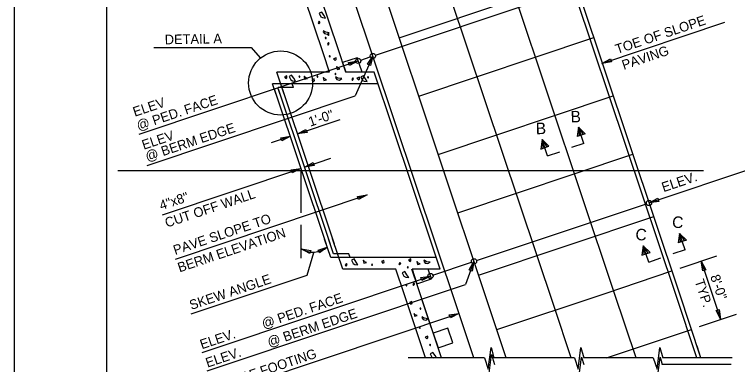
# Model space of a CAD drawing. Extents: x 0 to 272, y 0 to 188.
# Drawn here: x 0 to 94, y 79 to 124.5 of the extents above; entities that cross this region are included whole.
import ezdxf

# ---------------------------------------------------------------- set-up
doc = ezdxf.new("R2010")
doc.units = 0
for name, color, linetype in [('BORDER_ANNO_Cutsheet', 7, 'Continuous'), ('BRDG_ANNO_Anno-Sheet', 7, 'Continuous'), ('BRDG_ANNO_General-Notes', 7, 'Continuous'), ('BRDG_BASE_Hidden-Line', 7, 'Continuous'), ('BRDG_BASE_Obj-Line', 7, 'Continuous'), ('BRDG_BASE_Pattern', 7, 'Continuous'), ('BRDG_BASE_Roadway-Center-Lines', 7, 'Continuous')]:
    doc.layers.add(name, color=color, linetype=linetype)

msp = doc.modelspace()

# ---------------------------------------------------------------- linework, layer by layer
at = {"layer": 'BORDER_ANNO_Cutsheet'}
msp.add_lwpolyline([(0, 176), (272, 176), (272, 0), (0, 0)], close=True, dxfattribs=at)
at = {"layer": 'BRDG_ANNO_Anno-Sheet'}
msp.add_lwpolyline([(12, 172), (268, 172), (268, 4), (12, 4)], close=True, dxfattribs=at)
at = {"layer": 'BRDG_ANNO_General-Notes'}
for p, q in [((46.932, 119.228), (72.827, 127.893)), ((76.371, 118.156), (92.332, 123.497)), ((18.102, 120.234), (30.764, 120.234)), ((30.764, 120.234), (31.942, 118.866)), ((16.198, 108.945), (44.691, 118.478)), ((43.439, 118.279), (44.691, 118.478)), ((44.691, 118.478), (43.572, 117.884)), ((46.588, 119.099), (44.279, 113.92)), ((45.012, 118.586), (46.239, 118.996)), ((45.889, 118.043), (46.588, 119.099)), ((46.588, 119.099), (46.27, 117.873)), ((76.371, 118.156), (77.491, 118.75)), ((77.491, 118.75), (77.623, 118.355)), ((43.572, 117.884), (43.439, 118.279)), ((46.27, 117.873), (45.889, 118.043)), ((77.623, 118.355), (76.371, 118.156)), ((17.263, 104.88), (44.279, 113.92)), ((36.78, 108.983), (42.345, 110.845)), ((36.78, 108.983), (37.899, 109.578)), ((38.031, 109.182), (36.78, 108.983)), ((37.899, 109.578), (38.031, 109.182)), ((73.309, 109.876), (73.135, 108.63)), ((74.027, 107.744), (73.309, 109.876)), ((73.309, 109.876), (74.201, 108.989)), ((73.309, 109.876), (73.401, 108.72)), ((73.309, 109.876), (73.934, 108.9)), ((33.425, 107.861), (35.866, 108.678)), ((34.614, 108.478), (35.866, 108.678)), ((34.747, 108.083), (34.614, 108.478)), ((35.866, 108.678), (34.747, 108.083)), ((68.583, 108.267), (68.409, 107.022)), ((69.301, 106.135), (68.583, 108.267)), ((68.583, 108.267), (69.475, 107.381)), ((68.583, 108.267), (69.208, 107.291)), ((68.583, 108.267), (68.675, 107.112)), ((73.668, 108.81), (73.135, 108.63)), ((74.201, 108.989), (73.668, 108.81)), ((68.409, 107.022), (68.942, 107.201)), ((68.942, 107.201), (69.475, 107.381)), ((74.027, 107.744), (72.427, 107.205)), ((69.301, 106.135), (70.9, 106.673)), ((37.701, 104.67), (41.147, 105.824)), ((19.225, 98.488), (37.211, 104.506)), ((35.959, 104.307), (37.211, 104.506)), ((37.211, 104.506), (36.091, 103.912)), ((37.701, 104.67), (38.82, 105.265)), ((38.952, 104.869), (37.701, 104.67)), ((38.82, 105.265), (38.952, 104.869)), ((82.502, 100.022), (97.115, 104.912)), ((36.091, 103.912), (35.959, 104.307)), ((37.284, 98.712), (37.284, 104.251)), ((20.955, 92.725), (45.834, 101.049)), ((44.583, 100.85), (45.834, 101.049)), ((44.715, 100.455), (44.583, 100.85)), ((45.834, 101.049), (44.715, 100.455)), ((82.502, 100.022), (83.621, 100.616)), ((83.621, 100.616), (83.753, 100.221)), ((60.083, 92.521), (82.166, 99.91)), ((83.753, 100.221), (82.502, 100.022)), ((37.284, 92.855), (37.284, 97.18)), ((86.458, 96.061), (86.283, 94.815)), ((87.175, 93.929), (86.458, 96.061)), ((86.458, 96.061), (87.35, 95.174)), ((86.458, 96.061), (86.55, 94.905)), ((86.458, 96.061), (87.083, 95.085)), ((86.816, 94.995), (86.283, 94.815)), ((87.35, 95.174), (86.816, 94.995)), ((38.393, 93.434), (37.284, 94.047)), ((37.284, 94.047), (38.532, 93.827)), ((39.461, 93.885), (40.672, 94.257)), ((40.672, 94.257), (39.647, 93.512)), ((81.731, 94.453), (81.557, 93.207)), ((82.449, 92.32), (81.731, 94.453)), ((81.731, 94.453), (82.623, 93.566)), ((81.731, 94.453), (82.357, 93.476)), ((81.731, 94.453), (81.824, 93.297)), ((38.062, 90.648), (38.906, 93.579)), ((38.532, 93.827), (38.393, 93.434)), ((39.647, 93.512), (39.461, 93.885)), ((81.557, 93.207), (82.09, 93.386)), ((82.09, 93.386), (82.623, 93.566)), ((87.175, 93.929), (85.576, 93.39)), ((86.523, 91.524), (91.305, 93.124)), ((54.396, 90.618), (59.412, 92.296)), ((59.732, 92.406), (58.643, 89.43)), ((59.106, 91.304), (59.732, 92.406)), ((59.732, 92.406), (59.498, 91.161)), ((82.449, 92.32), (84.048, 92.858)), ((89.287, 92.449), (91.804, 84.926)), ((89.486, 91.197), (89.287, 92.449)), ((89.287, 92.449), (89.881, 91.33)), ((59.498, 91.161), (59.106, 91.304)), ((89.881, 91.33), (89.486, 91.197)), ((22.98, 85.602), (38.062, 90.648)), ((24.386, 80.577), (54.092, 90.516)), ((52.84, 90.317), (54.092, 90.516)), ((52.972, 89.922), (52.84, 90.317)), ((54.092, 90.516), (52.972, 89.922)), ((25.039, 78.187), (58.643, 89.43)), ((26.054, 75.048), (57.783, 85.664)), ((56.532, 85.465), (57.783, 85.664)), ((57.783, 85.664), (56.664, 85.07)), ((91.21, 86.045), (91.605, 86.177)), ((91.804, 84.926), (91.21, 86.045)), ((91.605, 86.177), (91.804, 84.926)), ((56.664, 85.07), (56.532, 85.465)), ((89.071, 83.941), (93.843, 85.538))]:
    msp.add_line(p, q, dxfattribs=at)
for centre, radius in [((34.602, 115.604), 4.162), ((46.588, 119.109), 0.343), ((82.491, 100.007), 0.343), ((59.74, 92.424), 0.343), ((54.08, 90.513), 0.343)]:
    msp.add_circle(centre, radius, dxfattribs=at)
msp.add_arc((38.824, 96.633), 3.01, 239.21951, 307.87987, dxfattribs=at)
at = {"layer": 'BRDG_BASE_Hidden-Line'}
for p, q in [((57.505, 86.496), (43.358, 128.776)), ((85.925, 88.224), (72.373, 128.728)), ((34.551, 114.128), (34.259, 115.001)), ((36.269, 115.005), (34.271, 115.005)), ((34.458, 114.405), (34.322, 114.812)), ((36.269, 115.005), (36.107, 115.492)), ((41.075, 94.631), (34.458, 114.405)), ((41.486, 93.402), (40.836, 95.344)), ((43.484, 93.402), (41.486, 93.402)), ((43.647, 92.915), (43.484, 93.402)), ((88.714, 79.889), (85.925, 88.224)), ((59.716, 79.889), (57.505, 86.496))]:
    msp.add_line(p, q, dxfattribs=at)
at = {"layer": 'BRDG_BASE_Obj-Line'}
for p, q in [((40.177, 119.375), (37.025, 128.794)), ((42.069, 120.024), (39.155, 128.733)), ((61.713, 86.525), (47.591, 128.731)), ((50.015, 121.488), (71.723, 128.752)), ((70.146, 86.534), (56.014, 128.772)), ((78.007, 88.253), (64.448, 128.776)), ((86.434, 88.278), (72.883, 128.778)), ((52.553, 113.902), (75.313, 121.517)), ((43.079, 117.005), (42.069, 120.024)), ((40.967, 117.013), (40.177, 119.375)), ((44.55, 118.887), (42.655, 118.246)), ((45.191, 116.993), (44.55, 118.887)), ((42.655, 118.246), (43.074, 117.01)), ((40.962, 117.005), (34.088, 117.005)), ((35.07, 114.153), (34.113, 117.013)), ((46.77, 117.005), (43.079, 117.005)), ((54.16, 94.918), (46.77, 117.005)), ((47.259, 115.505), (33.563, 115.505)), ((34.032, 114.102), (33.563, 115.505)), ((40.553, 94.612), (33.803, 114.787)), ((41.596, 94.649), (34.841, 114.838)), ((55.092, 106.315), (77.851, 113.93)), ((57.63, 98.728), (80.39, 106.344)), ((60.338, 90.633), (83.098, 98.248)), ((41.126, 92.902), (40.315, 95.326)), ((42.681, 91.406), (41.357, 95.362)), ((55.336, 91.402), (54.16, 94.918)), ((51.109, 92.902), (41.126, 92.902)), ((54.846, 92.902), (51.109, 92.902)), ((49.56, 91.402), (42.681, 91.402)), ((50.653, 88.203), (49.581, 91.409)), ((52.477, 88.978), (51.667, 91.397)), ((55.336, 91.402), (51.681, 91.402)), ((51.681, 91.402), (52.323, 89.508)), ((54.217, 90.149), (53.792, 91.404)), ((76.781, 88.265), (85.467, 91.171)), ((52.323, 89.508), (54.217, 90.149)), ((55.518, 79.889), (52.477, 88.978)), ((53.436, 79.889), (50.653, 88.203)), ((55.518, 79.889), (52.965, 87.52)), ((62.707, 83.555), (76.781, 88.265)), ((80.806, 79.889), (78.007, 88.253)), ((89.242, 79.889), (86.434, 88.278)), ((63.934, 79.889), (61.713, 86.525)), ((72.37, 79.889), (70.146, 86.534)), ((56.337, 83.738), (54.442, 83.097)), ((56.978, 81.844), (56.337, 83.738)), ((54.442, 83.097), (55.084, 81.202)), ((76.961, 79.889), (88.005, 83.584)), ((55.084, 81.202), (56.978, 81.844)), ((61.578, 78.4), (61.953, 81.206)), ((61.953, 81.206), (62.331, 79.879)), ((73.265, 78.4), (73.637, 81.205)), ((73.637, 81.205), (74.016, 79.881)), ((83.532, 78.402), (83.904, 81.207)), ((83.904, 81.207), (84.284, 79.883)), ((89.242, 79.889), (88.73, 81.417)), ((61.654, 77.529), (62.029, 80.336)), ((62.029, 80.336), (62.407, 79.009)), ((73.377, 77.281), (73.736, 79.988)), ((73.736, 79.988), (74.016, 79.01)), ((83.577, 77.281), (83.936, 79.99)), ((83.936, 79.99), (84.216, 79.012)), ((61.1, 79.88), (51.183, 79.88)), ((61.1, 79.88), (61.578, 78.4)), ((63.231, 79.879), (62.331, 79.879)), ((68.628, 79.879), (63.231, 79.879)), ((72.784, 79.879), (68.628, 79.879)), ((72.784, 79.879), (73.265, 78.4)), ((83.052, 79.881), (74.016, 79.881)), ((83.052, 79.881), (83.532, 78.402)), ((93.184, 79.013), (84.216, 79.012)), ((93.319, 79.883), (84.284, 79.883))]:
    msp.add_line(p, q, dxfattribs=at)
msp.add_circle((44.686, 118.477), 0.343, dxfattribs=at)
at = {"layer": 'BRDG_BASE_Pattern'}
for points in [[(39.606, 124.661), (39.831, 124.209), (40.057, 124.097), (40.45, 124.041), (40.225, 124.416), (39.944, 124.81)], [(39.472, 123.413), (39.565, 123.282), (39.677, 123.432), (39.696, 123.488), (39.603, 123.619)], [(40.13, 122.271), (40.299, 122.017), (40.646, 121.953), (40.928, 122.14), (40.491, 122.202), (40.154, 122.378)], [(40.374, 121.457), (40.445, 121.387), (40.501, 121.395), (40.501, 121.415), (40.501, 121.471), (40.482, 121.527), (40.449, 121.532), (40.421, 121.522), (40.412, 121.514), (40.399, 121.49)], [(40.745, 121.861), (40.815, 121.791), (40.871, 121.799), (40.871, 121.819), (40.871, 121.875), (40.852, 121.931), (40.82, 121.936), (40.792, 121.926), (40.782, 121.918), (40.769, 121.894)], [(40.684, 120.652), (40.777, 120.521), (40.889, 120.671), (40.908, 120.727), (40.815, 120.858)], [(40.907, 119.056), (40.977, 118.986), (41.033, 118.994), (41.033, 119.013), (41.033, 119.069), (41.014, 119.126), (40.981, 119.13), (40.953, 119.121), (40.944, 119.112), (40.931, 119.088)], [(41.485, 118.756), (41.676, 118.545), (41.826, 118.639), (41.808, 118.892)], [(41.864, 117.684), (41.93, 117.357), (42.282, 117.445), (42.024, 117.544), (41.893, 117.741)], [(35.694, 116.469), (35.919, 116.017), (36.145, 115.905), (36.538, 115.849), (36.313, 116.224), (36.032, 116.618)], [(41.647, 116.767), (41.718, 116.696), (41.773, 116.705), (41.773, 116.724), (41.773, 116.78), (41.754, 116.837), (41.722, 116.841), (41.694, 116.832), (41.684, 116.823), (41.671, 116.799)], [(35.088, 116.399), (35.279, 116.188), (35.429, 116.283), (35.412, 116.535)], [(36.968, 116.43), (37.038, 116.36), (37.094, 116.368), (37.094, 116.387), (37.094, 116.443), (37.075, 116.5), (37.042, 116.504), (37.014, 116.495), (37.005, 116.486), (36.992, 116.462)], [(37.656, 116.438), (37.721, 116.111), (38.074, 116.199), (37.815, 116.298), (37.685, 116.495)], [(38.657, 115.995), (38.848, 115.785), (38.998, 115.879), (38.98, 116.131)], [(39.324, 116.43), (39.395, 116.36), (39.45, 116.368), (39.45, 116.387), (39.45, 116.443), (39.431, 116.5), (39.399, 116.504), (39.371, 116.495), (39.361, 116.486), (39.348, 116.462)], [(40.147, 116.27), (40.213, 115.943), (40.565, 116.031), (40.307, 116.13), (40.176, 116.327)], [(41.739, 116.301), (41.909, 116.048), (42.255, 115.983), (42.537, 116.17), (42.1, 116.232), (41.763, 116.408)], [(43.842, 116.062), (43.935, 115.931), (44.047, 116.082), (44.067, 116.138), (43.973, 116.269)], [(44.515, 116.231), (44.706, 116.02), (44.856, 116.114), (44.838, 116.367)], [(45.019, 116.401), (45.245, 115.949), (45.47, 115.837), (45.864, 115.781), (45.639, 116.156), (45.358, 116.551)], [(45.889, 116.329), (45.96, 116.259), (46.016, 116.267), (46.016, 116.286), (46.016, 116.342), (45.996, 116.399), (45.964, 116.403), (45.936, 116.394), (45.926, 116.385), (45.913, 116.361)], [(43.012, 91.917), (43.106, 91.786), (43.218, 91.936), (43.237, 91.992), (43.144, 92.123)], [(43.811, 92.582), (44.037, 92.13), (44.262, 92.018), (44.656, 91.962), (44.431, 92.337), (44.149, 92.732)], [(45.348, 92.514), (45.414, 92.187), (45.766, 92.275), (45.508, 92.374), (45.377, 92.571)], [(47.707, 92.382), (47.898, 92.172), (48.048, 92.266), (48.03, 92.518)], [(49.982, 92.085), (50.075, 91.954), (50.187, 92.104), (50.207, 92.161), (50.113, 92.291)], [(51.208, 92.618), (51.399, 92.407), (51.549, 92.501), (51.532, 92.754)], [(52.317, 92.346), (52.383, 92.018), (52.735, 92.107), (52.477, 92.205), (52.346, 92.402)], [(53.223, 92.448), (53.393, 92.195), (53.74, 92.13), (54.021, 92.317), (53.584, 92.379), (53.247, 92.555)], [(46.414, 91.973), (46.484, 91.902), (46.54, 91.911), (46.54, 91.93), (46.54, 91.986), (46.521, 92.043), (46.488, 92.047), (46.46, 92.037), (46.451, 92.029), (46.438, 92.005)], [(51.06, 91.636), (51.13, 91.566), (51.186, 91.574), (51.186, 91.593), (51.186, 91.649), (51.167, 91.706), (51.135, 91.71), (51.106, 91.701), (51.097, 91.692), (51.084, 91.668)], [(50.41, 90.933), (50.635, 90.481), (50.861, 90.368), (51.254, 90.313), (51.029, 90.688), (50.748, 91.082)], [(50.891, 89.313), (50.962, 89.243), (51.018, 89.251), (51.018, 89.27), (51.018, 89.326), (50.998, 89.383), (50.966, 89.387), (50.938, 89.378), (50.928, 89.369), (50.916, 89.345)], [(51.8, 89.425), (51.893, 89.294), (52.005, 89.445), (52.025, 89.501), (51.931, 89.632)], [(51.346, 87.057), (51.537, 86.846), (51.687, 86.94), (51.669, 87.193)], [(51.95, 85.606), (52.016, 85.279), (52.368, 85.367), (52.109, 85.466), (51.979, 85.663)], [(52.712, 86.277), (52.783, 86.207), (52.839, 86.215), (52.839, 86.234), (52.839, 86.29), (52.819, 86.347), (52.787, 86.351), (52.759, 86.342), (52.749, 86.333), (52.736, 86.309)], [(52.957, 85.103), (53.126, 84.849), (53.473, 84.785), (53.755, 84.971), (53.318, 85.033), (52.981, 85.21)], [(52.611, 83.786), (52.682, 83.715), (52.737, 83.724), (52.737, 83.743), (52.737, 83.799), (52.718, 83.856), (52.686, 83.86), (52.658, 83.85), (52.648, 83.842), (52.635, 83.818)], [(53.399, 82.579), (53.591, 82.369), (53.741, 82.463), (53.723, 82.715)], [(53.958, 81.564), (54.028, 81.493), (54.084, 81.502), (54.084, 81.521), (54.084, 81.577), (54.065, 81.633), (54.033, 81.638), (54.005, 81.628), (53.995, 81.62), (53.982, 81.596)]]:
    msp.add_lwpolyline(points, close=True, dxfattribs=at)
for points in [[(54.844, 79.889), (54.671, 80.177), (54.389, 80.572), (54.051, 80.422)], [(54.051, 80.422), (54.277, 79.97), (54.441, 79.889)]]:
    msp.add_lwpolyline(points, dxfattribs=at)
at = {"layer": 'BRDG_BASE_Roadway-Center-Lines'}
for p, q in [((43.509, 104.189), (13.431, 104.189)), ((89.561, 104.189), (43.509, 104.189))]:
    msp.add_line(p, q, dxfattribs=at)

# ---------------------------------------------------------------- texts
at = {"layer": 'BRDG_ANNO_General-Notes'}
for s, height, rotation, p in [('TOE OF SLOPE', 1.25, 18.49999, (78.356, 119.357)), ('DETAIL A', 1.25, 1.1, (19.551, 120.625)), ('PAVING', 1.25, 18.49999, (79.213, 117.307)), ('ELEV  ', 1.25, 18.49992, (15.643, 111.209)), ('@ PED. FACE', 1.25, 18.49992, (16.114, 109.41)), ('1\'-0"', 1.25, 18.49998, (38.454, 109.92)), ('B', 1.5, 1.1, (72.31, 110.473)), ('@ BERM EDGE', 1.25, 18.49992, (17.257, 105.407)), ('B', 1.5, 1.1, (67.789, 108.942)), ('ELEV  ', 1.25, 18.49992, (16.808, 106.915)), ('ELEV.', 1.25, 18.49994, (84.382, 101.413)), ('CUT OFF WALL', 1.25, 18.49987, (19.806, 96.794)), ('4"x8"', 1.25, 18.49987, (19.083, 99.051)), ('PAVE SLOPE TO', 1.25, 18.50003, (20.886, 93.249)), ('C', 1.5, 356.1, (85.459, 96.809)), ('BERM ELEVATION', 1.25, 18.5, (21.464, 90.976)), ('C', 1.5, 356.1, (80.693, 95.204)), ('SKEW ANGLE', 1.25, 18.49997, (22.989, 86.1)), ('8\'-0"', 1.25, 288.50006, (90.435, 90.464)), ('TYP.', 1.25, 288.50006, (88.405, 89.867)), ('ELEV.        @ PED. FACE', 1.25, 18.50001, (24.366, 80.986)), ('ELEV.        @ BERM EDGE', 1.25, 18.50001, (25.095, 78.599)), ('TOE OF FOOTING', 1.25, 18.5, (25.842, 75.394))]:
    msp.add_text(s, height=height, rotation=rotation, dxfattribs=at).set_placement(p)

doc.saveas('drawing.dxf')
